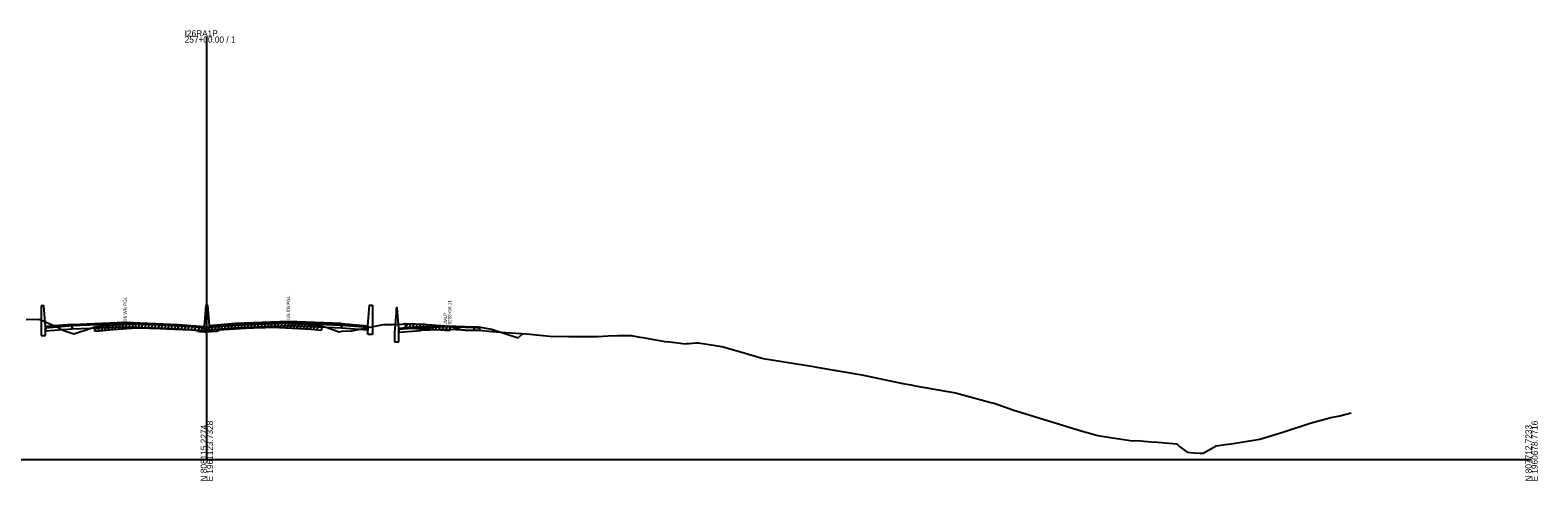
# Model space of a CAD drawing. Extents: x 1017 to 19997, y -1947 to 50737.
# Drawn here: x 10520 to 11203, y 6990 to 7194 of the extents above; entities that cross this region are included whole.
import ezdxf

# ---------------------------------------------------------------- set-up
doc = ezdxf.new("R2010")
doc.units = 0
for name, color, linetype in [('RD_GPK_XS_Cell', 7, 'Continuous'), ('RD_XS_Base', 7, 'Continuous'), ('RD_XS_ExGround', 7, 'Continuous'), ('RD_XS_ExPaveRet', 7, 'Continuous'), ('RD_XS_Greenside', 7, 'Continuous'), ('RD_XS_MedBWall', 7, 'Continuous'), ('RD_XS_Pave', 7, 'Continuous'), ('RD_XS_PaveOvlay', 7, 'Continuous'), ('RD_XS_TieSlope', 7, 'Continuous'), ('RD_XS_TX_Notes', 7, 'Continuous')]:
    doc.layers.add(name, color=color, linetype=linetype)

msp = doc.modelspace()

# ---------------------------------------------------------------- linework, layer by layer
at = {"layer": 'RD_GPK_XS_Cell'}
for p, q in [((10600, 7000), (10600, 7191.29)), ((10000, 7000), (10600, 7000)), ((10600, 7000), (11200, 7000))]:
    msp.add_line(p, q, dxfattribs=at)
at = {"layer": 'RD_XS_Base'}
for points in [[(10613, 7059.41), (10613, 7060.75)], [(10660.95, 7059.42), (10660.95, 7060.76)], [(10661, 7060.75), (10661, 7059.41)], [(10661, 7060.75), (10673, 7059.79)], [(10661, 7059.41), (10661, 7060.75)], [(10539, 7060.38), (10527, 7059.42)], [(10527, 7059.42), (10527, 7058.08)], [(10527, 7058.08), (10539, 7059.04)], [(10539, 7059.04), (10539, 7060.38)], [(10539.05, 7059.04), (10539, 7059.04)], [(10539.05, 7060.38), (10539.05, 7059.04)], [(10539.05, 7059.04), (10563, 7060.01), (10587, 7059.05)], [(10587, 7059.05), (10587, 7060.39)], [(10599, 7059.44), (10587, 7060.39)], [(10587, 7059.05), (10599, 7058.1)], [(10599, 7058.1), (10599, 7059.44)], [(10601, 7058.47), (10601, 7059.81)], [(10613, 7059.41), (10601, 7058.47)], [(10660.95, 7059.42), (10637, 7060.38), (10613, 7059.41)], [(10661, 7059.41), (10660.95, 7059.42)], [(10673, 7058.45), (10661, 7059.41)], [(10673, 7059.79), (10673, 7058.45)], [(10697, 7059.65), (10687, 7058.85)], [(10687, 7058.85), (10687, 7057.52)], [(10687, 7057.52), (10697, 7058.32)], [(10697, 7059.65), (10709, 7060.13), (10721, 7059.65)], [(10697, 7058.32), (10697, 7059.65)], [(10721, 7058.34), (10709, 7058.8), (10697, 7058.32)], [(10721, 7059.65), (10721, 7058.34)], [(10721, 7059.65), (10723, 7059.57), (10723.5, 7059.55)], [(10723.5, 7058.22), (10721, 7058.34)], [(10723.5, 7059.55), (10723.5, 7058.22)]]:
    msp.add_lwpolyline(points, dxfattribs=at)
at = {"layer": 'RD_XS_ExGround'}
msp.add_lwpolyline([(10518.14, 7063.25), (10524.07, 7063.39), (10531.84, 7060.1), (10535.54, 7058.08), (10537.49, 7057.49), (10539.83, 7056.74), (10548.03, 7059.53), (10549.35, 7060), (10551.41, 7060.19), (10557.4, 7060.77), (10568.05, 7061.43), (10569.14, 7061.5), (10578.73, 7061.22), (10580.84, 7061.16), (10581.77, 7061.12), (10592.77, 7060.6), (10594.58, 7060.38), (10595.63, 7060.25), (10595.81, 7059.93), (10596.58, 7059.87), (10598.83, 7059.7), (10600, 7059.75), (10600.54, 7059.77), (10601.64, 7059.82), (10604.73, 7060.05), (10604.88, 7060.16), (10605.51, 7060.26), (10605.69, 7060.55), (10607.7, 7060.76), (10620.04, 7061.48), (10621.35, 7061.51), (10631.97, 7061.74), (10632.93, 7061.69), (10644.57, 7061.1), (10645.69, 7061), (10652.02, 7060.48), (10654.09, 7059.73), (10657.38, 7058.55), (10659.99, 7057.68), (10661.35, 7058.02), (10665.68, 7058.12), (10679.98, 7061.05), (10682.47, 7061.02), (10684.22, 7061.01), (10688.52, 7061.21), (10690.07, 7061.4), (10698.9, 7061.09), (10699.85, 7061.01), (10710.01, 7060.32), (10713.08, 7059.35), (10715.66, 7058.53), (10716.8, 7058.5), (10723.36, 7058.4), (10729.2, 7057.79), (10735.36, 7057.39), (10744.74, 7056.76), (10755.36, 7055.68), (10763.9, 7055.51), (10764.32, 7055.51), (10777.32, 7055.62), (10781.83, 7055.82), (10786.02, 7055.97), (10789.06, 7056.03), (10792.22, 7056.06), (10796.12, 7055.35), (10797.54, 7055.08), (10807.42, 7053.35), (10809.76, 7053.14), (10816.75, 7052.29), (10817.43, 7052.37), (10818.54, 7052.44), (10821.49, 7052.67), (10822.65, 7052.75), (10833.23, 7051.13), (10841.22, 7048.85), (10852.01, 7045.67), (10872.9, 7042.28), (10874.72, 7042.01), (10876.11, 7041.75), (10896.62, 7038.26), (10915.18, 7034.39), (10918.97, 7033.78), (10920.83, 7033.31), (10939.1, 7030.17), (10955.63, 7025.55), (10956.59, 7025.38), (10965.55, 7022.27), (10996.08, 7012.89), (11002.52, 7011.17), (11003.56, 7010.86), (11008.19, 7010.1), (11012.31, 7009.38), (11017.22, 7008.65), (11019.07, 7008.37), (11021.47, 7008.47), (11024.41, 7008.18), (11027.82, 7007.94), (11030.53, 7007.77), (11039.28, 7006.96), (11040.49, 7005.87), (11043.35, 7003.66), (11043.96, 7003.21), (11046.94, 7002.98), (11049.96, 7002.79), (11051.2, 7002.79), (11056.14, 7005.54), (11057.19, 7006.13), (11061.28, 7006.66), (11063.95, 7007.05), (11076.98, 7009.15), (11087.78, 7012.39), (11099.71, 7016.43), (11109.01, 7018.97), (11113.12, 7019.75), (11118.29, 7021)], dxfattribs=at)
at = {"layer": 'RD_XS_ExPaveRet'}
for p, q in [((10555.35, 7058.58), (10556.41, 7060.68)), ((10556.85, 7058.72), (10557.9, 7060.81)), ((10558.35, 7058.83), (10559.39, 7060.9)), ((10559.85, 7058.93), (10560.89, 7060.99)), ((10561.35, 7059.02), (10562.39, 7061.08)), ((10562.85, 7059.11), (10563.89, 7061.17)), ((10564.35, 7059.2), (10565.39, 7061.27)), ((10565.85, 7059.3), (10566.89, 7061.36)), ((10567.35, 7059.39), (10568.39, 7061.45)), ((10568.85, 7059.48), (10569.85, 7061.48)), ((10570.35, 7059.46), (10571.34, 7061.44)), ((10571.85, 7059.42), (10572.84, 7061.39)), ((10573.35, 7059.38), (10574.34, 7061.35)), ((10574.85, 7059.33), (10575.84, 7061.3)), ((10576.35, 7059.29), (10577.34, 7061.26)), ((10577.85, 7059.25), (10578.84, 7061.22)), ((10579.35, 7059.2), (10580.34, 7061.17)), ((10580.85, 7059.16), (10581.83, 7061.11)), ((10582.35, 7059.09), (10583.33, 7061.04)), ((10583.85, 7059.02), (10584.83, 7060.97)), ((10585.35, 7058.95), (10586.33, 7060.9)), ((10586.85, 7058.88), (10587.83, 7060.83)), ((10588.35, 7058.81), (10589.33, 7060.76)), ((10589.85, 7058.74), (10590.83, 7060.69)), ((10591.35, 7058.67), (10592.33, 7060.62)), ((10604.85, 7058.14), (10606.08, 7060.59)), ((10606.35, 7058.62), (10607.41, 7060.73)), ((10607.85, 7058.77), (10608.89, 7060.83)), ((10609.35, 7058.85), (10610.39, 7060.92)), ((10610.85, 7058.94), (10611.89, 7061)), ((10612.35, 7059.03), (10613.39, 7061.09)), ((10613.85, 7059.12), (10614.89, 7061.18)), ((10615.35, 7059.21), (10616.39, 7061.27)), ((10616.85, 7059.29), (10617.89, 7061.35)), ((10618.35, 7059.38), (10619.39, 7061.44)), ((10619.85, 7059.47), (10620.87, 7061.5)), ((10621.35, 7059.51), (10622.37, 7061.53)), ((10622.85, 7059.54), (10623.87, 7061.56)), ((10624.35, 7059.57), (10625.37, 7061.6)), ((10625.85, 7059.61), (10626.87, 7061.63)), ((10627.35, 7059.64), (10628.37, 7061.66)), ((10628.85, 7059.67), (10629.87, 7061.69)), ((10630.35, 7059.7), (10631.37, 7061.73)), ((10631.85, 7059.74), (10632.83, 7061.69)), ((10633.35, 7059.67), (10634.33, 7061.62)), ((10634.85, 7059.59), (10635.83, 7061.54)), ((10636.35, 7059.51), (10637.33, 7061.46)), ((10637.85, 7059.44), (10638.83, 7061.39)), ((10639.35, 7059.36), (10640.33, 7061.31)), ((10640.85, 7059.29), (10641.83, 7061.24)), ((10642.35, 7059.21), (10643.33, 7061.16)), ((10643.85, 7059.14), (10644.83, 7061.08)), ((10645.35, 7059.03), (10646.31, 7060.95)), ((10646.85, 7058.91), (10647.82, 7060.83)), ((10648.35, 7058.78), (10649.32, 7060.7)), ((10649.85, 7058.66), (10650.82, 7060.58)), ((10690.07, 7059.4), (10690.07, 7061.4)), ((10690.07, 7059.4), (10691.05, 7061.37)), ((10691.57, 7059.35), (10692.55, 7061.32)), ((10693.07, 7059.3), (10694.05, 7061.26)), ((10694.57, 7059.24), (10695.55, 7061.21)), ((10696.07, 7059.19), (10697.05, 7061.15)), ((10697.57, 7059.14), (10698.55, 7061.1)), ((10699.07, 7059.07), (10700.03, 7060.99)), ((10700.57, 7058.96), (10701.54, 7060.89)), ((10702.07, 7058.86), (10703.04, 7060.79)), ((10703.57, 7058.75), (10704.54, 7060.69)), ((10705.07, 7058.65), (10706.04, 7060.59)), ((10549.35, 7058), (10550.4, 7060.1)), ((10549.35, 7058), (10549.35, 7060)), ((10549.35, 7058), (10551.41, 7058.19)), ((10550.85, 7058.14), (10551.91, 7060.24)), ((10551.41, 7058.19), (10557.4, 7058.77)), ((10552.35, 7058.28), (10553.41, 7060.39)), ((10553.85, 7058.43), (10554.91, 7060.53)), ((10557.4, 7058.77), (10568.05, 7059.43)), ((10568.05, 7059.43), (10569.14, 7059.5)), ((10569.14, 7059.5), (10578.73, 7059.22)), ((10578.73, 7059.22), (10580.84, 7059.16)), ((10580.84, 7059.16), (10581.77, 7059.12)), ((10581.77, 7059.12), (10592.77, 7058.6)), ((10592.77, 7058.6), (10594.58, 7058.38)), ((10592.85, 7058.59), (10593.8, 7060.48)), ((10594.35, 7058.41), (10595.3, 7060.29)), ((10594.58, 7058.38), (10595.63, 7058.25)), ((10595.63, 7058.25), (10595.81, 7057.93)), ((10595.81, 7057.93), (10596.58, 7057.87)), ((10595.85, 7057.92), (10596.82, 7059.85)), ((10596.58, 7057.87), (10598.83, 7057.7)), ((10597.35, 7057.81), (10598.32, 7059.74)), ((10598.83, 7057.7), (10600, 7057.75)), ((10598.85, 7057.7), (10599.88, 7059.74)), ((10600, 7057.75), (10600.54, 7057.77)), ((10600.35, 7057.76), (10601.38, 7059.81)), ((10600.54, 7057.77), (10601.64, 7057.82)), ((10601.64, 7057.82), (10604.73, 7058.05)), ((10601.85, 7057.84), (10602.89, 7059.91)), ((10603.35, 7057.95), (10604.39, 7060.03)), ((10604.73, 7058.05), (10604.88, 7058.16)), ((10604.88, 7058.16), (10605.51, 7058.26)), ((10605.51, 7058.26), (10605.69, 7058.55)), ((10605.69, 7058.55), (10607.7, 7058.76)), ((10607.7, 7058.76), (10620.04, 7059.48)), ((10620.04, 7059.48), (10621.35, 7059.51)), ((10621.35, 7059.51), (10631.97, 7059.74)), ((10631.97, 7059.74), (10632.93, 7059.69)), ((10632.93, 7059.69), (10644.57, 7059.1)), ((10644.57, 7059.1), (10645.69, 7059)), ((10645.69, 7059), (10652.02, 7058.48)), ((10652.02, 7060.48), (10652.02, 7058.48)), ((10690.07, 7059.4), (10698.9, 7059.09)), ((10698.9, 7059.09), (10699.85, 7059.01)), ((10699.85, 7059.01), (10710.01, 7058.32)), ((10706.57, 7058.55), (10707.54, 7060.48)), ((10708.07, 7058.45), (10709.04, 7060.38)), ((10710.01, 7060.32), (10710.01, 7058.32))]:
    msp.add_line(p, q, dxfattribs=at)
at = {"layer": 'RD_XS_Greenside'}
for points in [[(10723, 7059.89), (10729, 7058.93)], [(10729, 7058.93), (10741, 7054.93)]]:
    msp.add_lwpolyline(points, dxfattribs=at)
at = {"layer": 'RD_XS_MedBWall'}
for points in [[(10527, 7060.1), (10526.25, 7069.44), (10525, 7069.44)], [(10525, 7069.44), (10525, 7056.1)], [(10599, 7060.1), (10599.75, 7069.81), (10600.25, 7069.81), (10601, 7060.47)], [(10673, 7060.47), (10673.75, 7069.81), (10675, 7069.81)], [(10675, 7069.81), (10675, 7056.47)], [(10687, 7059.17), (10686.25, 7068.51), (10685.75, 7068.51)], [(10685.75, 7068.51), (10685.75, 7066.51)], [(10685.75, 7066.51), (10685, 7057.17)], [(10525, 7056.1), (10527, 7056.1)], [(10527, 7056.1), (10527, 7060.1)], [(10599, 7058.1), (10599, 7060.1)], [(10601, 7058.1), (10599, 7058.1)], [(10601, 7060.47), (10601, 7058.1)], [(10673, 7056.47), (10673, 7060.47)], [(10675, 7056.47), (10673, 7056.47)], [(10685, 7057.17), (10685, 7053.17)], [(10687, 7053.17), (10687, 7059.17)], [(10685, 7053.17), (10687, 7053.17)]]:
    msp.add_lwpolyline(points, dxfattribs=at)
at = {"layer": 'RD_XS_Pave'}
for points in [[(10539, 7060.72), (10527, 7059.76)], [(10539, 7060.38), (10539, 7060.72)], [(10539.05, 7060.72), (10563, 7061.69), (10587, 7060.73)], [(10587, 7060.39), (10563, 7061.35), (10539.05, 7060.38)], [(10539.05, 7060.38), (10539.05, 7060.72)], [(10587, 7060.73), (10587, 7060.39)], [(10587, 7060.73), (10599, 7059.78)], [(10613, 7061.09), (10601, 7060.15)], [(10601, 7059.81), (10613, 7060.75)], [(10660.95, 7061.1), (10637, 7062.05), (10613, 7061.09)], [(10613, 7060.75), (10637, 7061.72), (10660.95, 7060.76)], [(10613, 7061.09), (10613, 7060.75)], [(10660.95, 7060.76), (10660.95, 7061.1)], [(10660.95, 7061.1), (10661, 7061.09)], [(10661, 7060.75), (10660.95, 7060.76)], [(10661, 7061.09), (10661, 7060.75)], [(10661, 7060.75), (10661, 7061.09)], [(10527, 7059.76), (10527, 7059.42)], [(10539.05, 7060.38), (10539, 7060.38)], [(10599, 7059.78), (10599, 7059.44)], [(10601, 7060.15), (10601, 7059.81)], [(10673, 7060.13), (10673, 7059.79)]]:
    msp.add_lwpolyline(points, dxfattribs=at)
at = {"layer": 'RD_XS_PaveOvlay'}
for points in [[(10539, 7061.06), (10527, 7060.1)], [(10539.05, 7061.06), (10539, 7061.06)], [(10539, 7061.06), (10539, 7060.72)], [(10539, 7060.72), (10539.05, 7060.72)], [(10539.05, 7061.06), (10563, 7062.02), (10587, 7061.06)], [(10539.05, 7060.72), (10539.05, 7061.06)], [(10587, 7061.06), (10587, 7060.73)], [(10587, 7061.06), (10599, 7060.1)], [(10613, 7061.43), (10601, 7060.47)], [(10660.95, 7061.43), (10637, 7062.39), (10613, 7061.43)], [(10613, 7061.43), (10613, 7061.09)], [(10660.95, 7061.1), (10660.95, 7061.43)], [(10660.95, 7061.43), (10661, 7061.43)], [(10661, 7061.43), (10661, 7061.09)], [(10661, 7061.43), (10673, 7060.47)], [(10661, 7061.09), (10661, 7061.43)], [(10673, 7060.13), (10661, 7061.09)], [(10527, 7060.1), (10527, 7059.76)], [(10599, 7060.1), (10599, 7059.78)], [(10601, 7060.47), (10601, 7060.15)], [(10673, 7060.47), (10673, 7060.13)], [(10697, 7059.97), (10687, 7059.17)], [(10687, 7058.85), (10697, 7059.65)], [(10687, 7059.17), (10687, 7058.85)], [(10697, 7059.97), (10709, 7060.45), (10721, 7059.97)], [(10721, 7059.65), (10709, 7060.13), (10697, 7059.65)], [(10697, 7059.65), (10697, 7059.97)], [(10721, 7059.97), (10721, 7059.65)], [(10721, 7059.97), (10723, 7059.89)], [(10723, 7059.57), (10721, 7059.65)], [(10723, 7059.89), (10723, 7059.57)]]:
    msp.add_lwpolyline(points, dxfattribs=at)
at = {"layer": 'RD_XS_TieSlope'}
msp.add_lwpolyline([(10741, 7054.93), (10742.93, 7056.86)], dxfattribs=at)

# ---------------------------------------------------------------- texts
at = {"layer": 'RD_GPK_XS_Cell'}
for s, p in [('257+00.00 / 1', (10590, 7188.49)), ('I26RA1P', (10590, 7191.29))]:
    msp.add_text(s, height=2.8, dxfattribs=at).set_placement(p)
for s, p in [('N 808115.2274', (10600, 6990)), ('E 1961123.7328', (10602.8, 6990)), ('N 807712.7233', (11200, 6990)), ('E 1960678.7716', (11202.8, 6990))]:
    msp.add_text(s, height=2.8, rotation=90, dxfattribs=at).set_placement(p)
at = {"layer": 'RD_XS_TX_Notes'}
for s, p in [('I26 WB PGL', (10563.75, 7062.02)), ('I26 EB PGL', (10637.75, 7063.12)), (' 9258+56.11', (10710.73, 7060.44)), (' JMLP', (10708.77, 7060.44))]:
    msp.add_text(s, height=1.5, rotation=90, dxfattribs=at).set_placement(p)

doc.saveas('drawing.dxf')
